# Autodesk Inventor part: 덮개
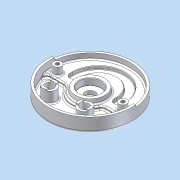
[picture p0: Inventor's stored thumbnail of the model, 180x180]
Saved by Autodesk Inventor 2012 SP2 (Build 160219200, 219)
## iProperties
Company: 한국ATC센터
Created: 2015-04
Part Number: 덮개
Document SubType Name: Modeling
Designer: KYOUNG IL JANG
Density: 2.71 g/cm^3
Material: 알루미늄-6061
Author: KYOUNG IL JANG
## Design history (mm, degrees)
sketch "스케치1"
  geometry: L1 (-59, -19)-(-59, 19); L2 (59, 19)-(59, -19); L3 (-41, 19)-(-41, -19); L4 (41, -19)-(41, 19); L5 (59, 5)-(41, 5); L6 (-41, 5)-(-59, 5); C1 r 90 at (0, 0); C2 r 95 at (0, 0); A1 r 59 centre (0, 19) between (59, 19) and (-59, 19); A2 r 59 centre (0, -19) between (-59, -19) and (59, -19); A3 r 41 centre (0, -19) between (-41, -19) and (41, -19); A4 r 41 centre (0, 19) between (41, 19) and (-41, 19); 2 further points
  constraints: 12 end point, 8 point on circle, 6 centre point, 4 point on line, 4 tangent, 2 parallel, 2 perpendicular, 1 coincident, 1 collinear, 1 horizontal alignment, 1 midpoint, 1 vertical, 1 vertical alignment, 3 other
  dimensions: "d2" = 180 diameter of C1; "d3" = 156 dimension on A2 A1; "d4" = 118 distance between parallel lines of L2 L1; "d5" = 18 distance between parallel lines of L2 L4; "d8" = 190 diameter of C2; "d121" = 5 distance from line of L5 point (0, 0)
extrude "돌출1" new body sketch "스케치1" distance "d6" = 14; taper "d7" = 0 deg
extrude "돌출2" join sketch "스케치1" distance "d9" = 13; taper "d10" = 0 deg
extrude "돌출3" cut sketch "스케치1" distance "d11" = 7; taper "d12" = 0 deg
sketch "스케치2"
  geometry: C1 r 11.5 at (0, 0); 1 further point
  constraints: 1 centre point, 1 coincident
  dimensions: "d13" = 23 diameter of C1
extrude "돌출4" cut sketch "스케치2" stored distance "d14" = 7; taper "d15" = 0 deg
fillet "모깎기1"
fillet "모깎기2"
sketch "스케치3"
  geometry: L1 (-89.658, 7.844)-(-94.638, 8.28); L2 (89.658, 7.844)-(94.638, 8.28); L3 (0, 0)-(0, -90); A1 r 95 centre (0, 0) between (-94.638, 8.28) and (94.638, 8.28) reference; A2 r 90 centre (0, 0) between (-89.658, 7.844) and (89.658, 7.844) reference; 1 further point
  constraints: 6 end point, 5 point on circle, 1 point on line, 1 vertical, 1 other
  dimensions: "d16" = 190 deg dimension on L2 L1
extrude "돌출5" join sketch "스케치3" distance "d17" = 5; taper "d18" = 0 deg
hole "구멍1" diameter "d21" = 50; stored, may be unused: countersink angle "d25" = 90 deg, drill point angle "d27" = 0 deg; dims "d19" = 10, "d20" = 10, "d22" = 6, "d23" = 4, "d24" = 2, "d26" = 5
fillet "모깎기3" dims "d28" = 0.3
fillet "모깎기5" dims "d30" = 3
sketch "스케치4"
  geometry: C1 r 35 at (0, 0); C2 r 25 at (0, 0); 1 further point
  constraints: 2 centre point, 1 coincident
  dimensions: "d32" = 70 diameter of C1 (derived); "d36" = 10 radial gap between concentric circles of C1 C2
extrude "돌출6" join sketch "스케치4" distance "d33" = 10; taper "d34" = 0 deg
feature "면 기울기2" dims angle "d37" = 10 deg
chamfer "모따기1" distance "d39" = 1; stored, may be unused: second distance "d40" = 2, angle "d41" = 45 deg
fillet "모깎기7" dims "d42" = 5
sketch "스케치5"
  geometry: L1 (-40.249, -12)-(-89.196, -12); L2 (40.249, -12)-(89.196, -12); A1 r 90 centre (0, 0) between (-89.196, -12) and (89.196, -12) reference; A2 r 42 centre (0, 0) between (-40.249, -12) and (40.249, -12); 1 further point
  constraints: 4 end point, 4 point on circle, 1 centre point, 1 collinear, 1 horizontal, 1 point on line
  dimensions: "d43" = 48 radial gap between concentric circles of A1 A2; "d44" = 12 distance from line of point (0, 0) L1
extrude "돌출7" cut sketch "스케치5" stored distance "d45" = 10; taper "d46" = 0 deg
fillet "모깎기8" dims "d47" = 10
chamfer "모따기2" distance "d49" = 1; stored, may be unused: second distance "d50" = 2, angle "d51" = 45 deg
sketch "스케치8"
  geometry: C1 r 9 at (74, 0); C2 r 9 at (-74, 0); A1 r 74 centre (0, 0) between (74, 0) and (-74, 0); 1 further point
  constraints: 3 centre point, 2 horizontal alignment, 2 point on circle, 1 coincident, 1 equal radius
  dimensions: "d64" = 18 diameter of C1; "d65" = 148 diameter of A1
extrude "돌출9" join sketch "스케치8" stored distance "d66" = 5; taper "d67" = 0 deg
sketch "스케치11"
  geometry: C1 r 15 at (40, -52); C2 r 15 at (-40, -52); 1 further point
  constraints: 2 centre point, 1 equal radius, 1 horizontal alignment
  dimensions: "d82" = 52 vertical distance of point (0, 0) C1.centre; "d83" = 30 diameter of C1; "d84" = 80 distance of C2.centre C1.centre; "d85" = 40 horizontal distance of point (0, 0) C1.centre (= 0.5 x d84)
extrude "돌출10" join sketch "스케치11" stored distance "d86" = 10; taper "d87" = 0 deg
node "구멍3"
node "구멍5"
hole "구멍6" diameter "d92" = 20; stored, may be unused: countersink angle "d96" = 90 deg, drill point angle "d98" = 118 deg; dims "d90" = 10, "d91" = 10, "d93" = 6, "d94" = 4, "d95" = 2, "d97" = 8
hole "구멍7" diameter "d101" = 20; stored, may be unused: countersink angle "d105" = 90 deg, drill point angle "d107" = 118 deg; dims "d99" = 10, "d100" = 10, "d102" = 6, "d103" = 4, "d104" = 2, "d106" = 8
fillet "모깎기13" dims "d108" = 3
sketch "스케치13"
  geometry: L1 (-20.252, -58)-(-26, -58); L2 (-42, -58)-(-47.748, -58); L3 (-20.252, -46)-(-26, -46); L4 (-42, -46)-(-47.748, -46); L5 (-108, -65.748)-(-108, -60); L6 (-108, -44)-(-108, -38.252); L7 (-120, -44)-(-120, -38.252); L8 (-120, -60)-(-120, -65.748); A1 r 15 centre (-34, -52) between (-20.252, -58) and (-47.748, -58) reference; A2 r 10 centre (-34, -52) between (-26, -58) and (-42, -58) reference; A3 r 15 centre (-114, -52) between (-108, -65.748) and (-108, -38.252) reference; A4 r 10 centre (-114, -52) between (-108, -60) and (-108, -44) reference; 1 further point
  constraints: 16 end point, 16 point on circle, 3 equal length, 3 point on line, 2 collinear, 1 horizontal, 1 perpendicular
  dimensions: "d114" = 12 distance between parallel lines of L4 L2; "d115" = 6 distance from line of A1.centre L2 (= 0.5 x d114); "d116" = 12 distance between parallel lines of L8 L5 (= d114); "d117" = 6 distance from line of A3.centre L5 (= d115)
extrude "돌출12" join sketch "스케치13" distance "d118" = 3; taper "d119" = 0 deg
fillet "모깎기14" dims "d120" = 1
node "솔리드1"
sketch "스케치9"
  geometry: 1 further point
hole "구멍2" sketch "스케치9" diameter "d68" = 8.376; stored, may be unused: countersink angle "d72" = 90 deg, drill point angle "d74" = 120 deg; dims "d69" = 16, "d70" = 4, "d71" = 2, "d73" = 21
sketch "스케치10"
  geometry: 1 further point
hole "구멍4" sketch "스케치10" diameter "d75" = 8.376; stored, may be unused: countersink angle "d79" = 90 deg, drill point angle "d81" = 120 deg; dims "d76" = 16, "d77" = 4, "d78" = 2, "d80" = 21
